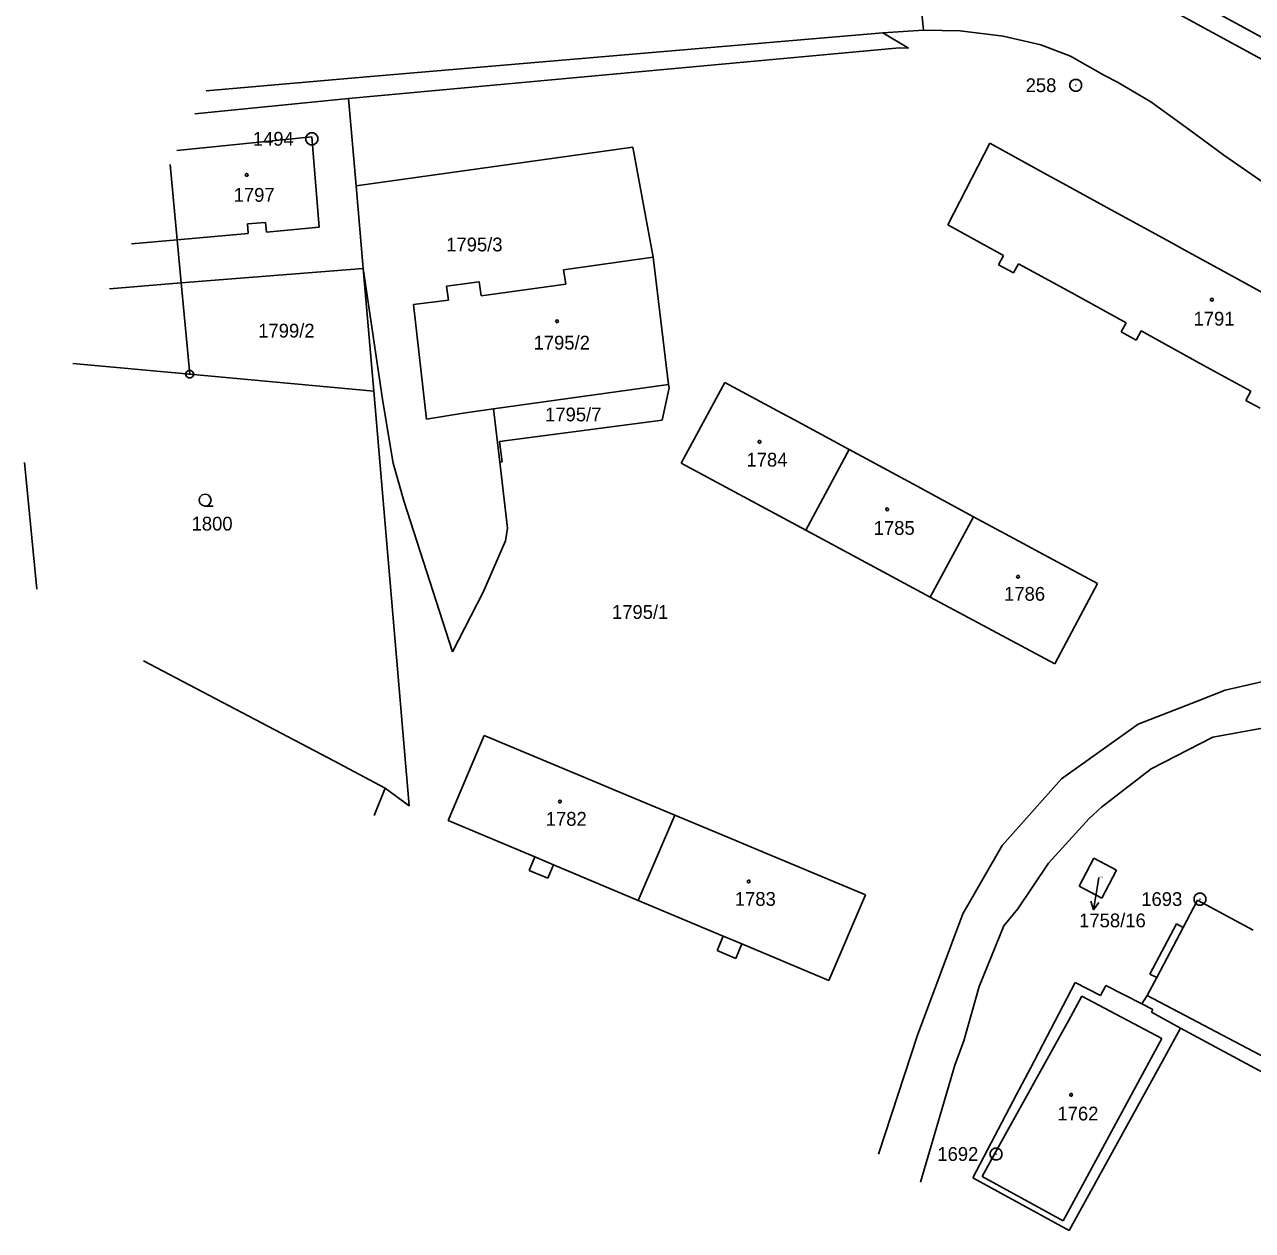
# Model space of a CAD drawing. Extents: x -528274 to -527531, y -1079304 to -1078580.
# Drawn here: x -528274.4 to -528123, y -1079056.9 to -1078908.2 of the extents above; entities that cross this region are included whole.
import ezdxf

# ---------------------------------------------------------------- set-up
doc = ezdxf.new("R2010")
doc.units = 0
doc.layers.add('katastrální mapa', color=7, linetype='Continuous')

msp = doc.modelspace()

# ---------------------------------------------------------------- linework, layer by layer
at = {"layer": 'katastrální mapa'}
for p, q in [((-528164.53, -1078898.32), (-528163.54, -1078908.83)), ((-528069.83, -1078938.11), (-528132.09, -1078904.11)), ((-528007.07, -1078975.18), (-528133.47, -1078906.09)), ((-528168.55, -1078909.17), (-528232.69, -1078914.64)), ((-528163.54, -1078908.83), (-528168.55, -1078909.17)), ((-528168.55, -1078909.17), (-528165.37, -1078911.05)), ((-528163.54, -1078908.83), (-528158.99, -1078908.92)), ((-528158.99, -1078908.92), (-528153.69, -1078909.6)), ((-528153.69, -1078909.6), (-528149.06, -1078910.66)), ((-528166.47, -1078911.04), (-528234.43, -1078917.27)), ((-528165.37, -1078911.05), (-528166.47, -1078911.04)), ((-528149.06, -1078910.66), (-528145.38, -1078912.05)), ((-528145.38, -1078912.05), (-528141.22, -1078914.44)), ((-528252, -1078916.32), (-528232.69, -1078914.64)), ((-528144.79, -1078915.64), (-528144.69, -1078915.64)), ((-528141.22, -1078914.44), (-528139.61, -1078915.25)), ((-528139.61, -1078915.25), (-528135.47, -1078917.68)), ((-528234.43, -1078917.27), (-528253.41, -1078919.19)), ((-528233.51, -1078928.06), (-528234.43, -1078917.27)), ((-528135.47, -1078917.68), (-528130.7, -1078921.13)), ((-528130.7, -1078921.13), (-528126.5, -1078924.27)), ((-528255.6, -1078923.69), (-528238.95, -1078922.01)), ((-528239.01, -1078922.25), (-528238.91, -1078922.25)), ((-528238.95, -1078922.01), (-528238.07, -1078933.14)), ((-528199.37, -1078923.27), (-528233.51, -1078928.06)), ((-528196.86, -1078936.86), (-528199.37, -1078923.27)), ((-528155.36, -1078922.8), (-528160.53, -1078932.88)), ((-528148.26, -1078926.69), (-528155.36, -1078922.8)), ((-528126.5, -1078924.27), (-528121.57, -1078927.7)), ((-528256.46, -1078925.44), (-528255.59, -1078934.71)), ((-528146.77, -1078927.51), (-528148.26, -1078926.69)), ((-528140.01, -1078931.21), (-528146.77, -1078927.51)), ((-528233.51, -1078928.06), (-528232.64, -1078938.27)), ((-528133.06, -1078935.02), (-528140.01, -1078931.21)), ((-528246.81, -1078933.95), (-528255.59, -1078934.71)), ((-528244.68, -1078932.57), (-528246.91, -1078932.76)), ((-528246.91, -1078932.76), (-528246.81, -1078933.95)), ((-528244.57, -1078933.76), (-528244.68, -1078932.57)), ((-528238.07, -1078933.14), (-528244.57, -1078933.76)), ((-528160.53, -1078932.88), (-528153.64, -1078936.66)), ((-528261.22, -1078935.19), (-528255.59, -1078934.71)), ((-528255.59, -1078934.71), (-528255.09, -1078940.04)), ((-528131.68, -1078935.77), (-528133.06, -1078935.02)), ((-528207.91, -1078938.4), (-528196.86, -1078936.86)), ((-528196.86, -1078936.86), (-528194.96, -1078952.55)), ((-528153.64, -1078936.66), (-528154.26, -1078937.8)), ((-528124.66, -1078939.62), (-528131.68, -1078935.77)), ((-528255.09, -1078940.04), (-528232.64, -1078938.27)), ((-528232.64, -1078938.27), (-528231.34, -1078953.37)), ((-528230.2, -1078954.68), (-528232.64, -1078938.27)), ((-528207.66, -1078940.2), (-528207.91, -1078938.4)), ((-528154.26, -1078937.8), (-528152.42, -1078938.8)), ((-528152.42, -1078938.8), (-528151.8, -1078937.67)), ((-528151.8, -1078937.67), (-528145.23, -1078941.27)), ((-528263.93, -1078940.74), (-528255.09, -1078940.04)), ((-528255.09, -1078940.04), (-528254.03, -1078951.3)), ((-528218.33, -1078939.9), (-528222.34, -1078940.43)), ((-528218.1, -1078941.61), (-528218.33, -1078939.9)), ((-528117.65, -1078943.46), (-528124.66, -1078939.62)), ((-528222.34, -1078940.43), (-528222.12, -1078942.14)), ((-528207.66, -1078940.2), (-528218.1, -1078941.61)), ((-528145.23, -1078941.27), (-528138.52, -1078944.95)), ((-528222.12, -1078942.14), (-528226.45, -1078942.71)), ((-528226.45, -1078942.71), (-528224.84, -1078956.83)), ((-528138.52, -1078944.95), (-528139.14, -1078946.07)), ((-528139.14, -1078946.07), (-528137.29, -1078947.08)), ((-528137.29, -1078947.08), (-528136.68, -1078945.96)), ((-528136.68, -1078945.96), (-528129.93, -1078949.67)), ((-528268.44, -1078949.98), (-528254.03, -1078951.3)), ((-528129.93, -1078949.67), (-528123.16, -1078953.38)), ((-528254.15, -1078951.3), (-528253.91, -1078951.3)), ((-528254.03, -1078951.3), (-528231.34, -1078953.37)), ((-528231.34, -1078953.37), (-528226.98, -1079004.55)), ((-528216.55, -1078955.58), (-528194.96, -1078952.55)), ((-528194.91, -1078952.97), (-528195.74, -1078956.97)), ((-528194.96, -1078952.55), (-528194.91, -1078952.97)), ((-528193.4, -1078962.25), (-528188.04, -1078952.31)), ((-528188.04, -1078952.31), (-528181, -1078956.11)), ((-528123.16, -1078953.38), (-528123.79, -1078954.52)), ((-528228.95, -1078962.25), (-528230.2, -1078954.68)), ((-528123.79, -1078954.52), (-528121.99, -1078955.5)), ((-528224.84, -1078956.83), (-528220.3, -1078956.11)), ((-528220.3, -1078956.11), (-528216.55, -1078955.58)), ((-528215.79, -1078962.13), (-528216.55, -1078955.58)), ((-528181, -1078956.11), (-528179.52, -1078956.9)), ((-528195.74, -1078956.97), (-528215.84, -1078959.61)), ((-528179.52, -1078956.9), (-528172.69, -1078960.59)), ((-528215.84, -1078959.61), (-528215.51, -1078962.09)), ((-528172.69, -1078960.59), (-528178.04, -1078970.52)), ((-528172.69, -1078960.59), (-528165.82, -1078964.29)), ((-528272.87, -1078977.83), (-528274.4, -1078962.2)), ((-528227.64, -1078966.91), (-528228.95, -1078962.25)), ((-528215.51, -1078962.09), (-528215.79, -1078962.13)), ((-528215.79, -1078962.13), (-528214.84, -1078970.28)), ((-528178.04, -1078970.52), (-528193.4, -1078962.25)), ((-528165.82, -1078964.29), (-528164.32, -1078965.1)), ((-528164.32, -1078965.1), (-528157.34, -1078968.87)), ((-528221.63, -1078985.54), (-528227.64, -1078966.91)), ((-528214.84, -1078970.28), (-528215.1, -1078971.85)), ((-528157.34, -1078968.87), (-528162.69, -1078978.78)), ((-528157.34, -1078968.87), (-528150.68, -1078972.46)), ((-528215.1, -1078971.85), (-528217.84, -1078978.19)), ((-528162.69, -1078978.78), (-528178.04, -1078970.52)), ((-528150.68, -1078972.46), (-528149.16, -1078973.28)), ((-528149.16, -1078973.28), (-528142.07, -1078977.1)), ((-528142.07, -1078977.1), (-528147.34, -1078987.04)), ((-528217.84, -1078978.19), (-528221.63, -1078985.54)), ((-528147.34, -1078987.04), (-528162.69, -1078978.78)), ((-528236.27, -1078999.01), (-528259.73, -1078986.65)), ((-528126.3, -1078990.26), (-528117, -1078988.13)), ((-528129.66, -1078991.6), (-528126.3, -1078990.26)), ((-528137.05, -1078994.47), (-528129.66, -1078991.6)), ((-528146.52, -1079001.22), (-528137.05, -1078994.47)), ((-528123.53, -1078995.3), (-528114.72, -1078993.64)), ((-528222.17, -1079006.35), (-528217.73, -1078995.86)), ((-528217.73, -1078995.86), (-528203.45, -1079001.82)), ((-528135.44, -1078999.98), (-528127.83, -1078996.06)), ((-528127.83, -1078996.06), (-528123.53, -1078995.3)), ((-528229.91, -1079002.36), (-528236.27, -1078999.01)), ((-528141.57, -1079004.7), (-528135.44, -1078999.98)), ((-528203.45, -1079001.82), (-528201.59, -1079002.6)), ((-528153.84, -1079009.45), (-528146.52, -1079001.22)), ((-528229.91, -1079002.36), (-528231.3, -1079005.74)), ((-528226.98, -1079004.55), (-528229.91, -1079002.36)), ((-528201.59, -1079002.6), (-528194.2, -1079005.69)), ((-528143.08, -1079006.1), (-528141.57, -1079004.7)), ((-528211.48, -1079010.84), (-528222.17, -1079006.35)), ((-528194.2, -1079005.69), (-528198.7, -1079016.21)), ((-528194.2, -1079005.69), (-528186.81, -1079008.77)), ((-528148.11, -1079011.63), (-528143.08, -1079006.1)), ((-528186.81, -1079008.77), (-528184.94, -1079009.55)), ((-528184.94, -1079009.55), (-528170.68, -1079015.51)), ((-528158.67, -1079017.88), (-528153.84, -1079009.45)), ((-528212.18, -1079012.51), (-528211.48, -1079010.84)), ((-528211.48, -1079010.84), (-528209.16, -1079011.82)), ((-528144.32, -1079014.46), (-528142.5, -1079011.01)), ((-528142.5, -1079011.01), (-528139.72, -1079012.48)), ((-528209.86, -1079013.48), (-528212.18, -1079012.51)), ((-528209.16, -1079011.82), (-528209.86, -1079013.48)), ((-528198.7, -1079016.21), (-528209.16, -1079011.82)), ((-528151.91, -1079017.26), (-528148.11, -1079011.63)), ((-528139.72, -1079012.48), (-528141.54, -1079015.92)), ((-528141.9, -1079013.4), (-528142.07, -1079014.4)), ((-528170.68, -1079015.51), (-528175.21, -1079026.08)), ((-528141.54, -1079015.92), (-528144.32, -1079014.46)), ((-528142.57, -1079017.36), (-528142.07, -1079014.4)), ((-528188.23, -1079020.61), (-528198.7, -1079016.21)), ((-528153.6, -1079019.34), (-528151.91, -1079017.26)), ((-528129.73, -1079016.2), (-528131.5, -1079019.55)), ((-528129.73, -1079016.2), (-528122.87, -1079019.88)), ((-528129.47, -1079016.05), (-528129.37, -1079016.05)), ((-528158.67, -1079017.88), (-528164.27, -1079032.84)), ((-528156.65, -1079026.82), (-528153.6, -1079019.34)), ((-528132.34, -1079019.1), (-528135.6, -1079025.3)), ((-528131.5, -1079019.55), (-528134.76, -1079025.74)), ((-528131.5, -1079019.55), (-528132.34, -1079019.1)), ((-528188.97, -1079022.39), (-528188.23, -1079020.61)), ((-528188.23, -1079020.61), (-528185.93, -1079021.58)), ((-528185.93, -1079021.58), (-528186.68, -1079023.36)), ((-528175.21, -1079026.08), (-528185.93, -1079021.58)), ((-528186.68, -1079023.36), (-528188.97, -1079022.39)), ((-528144.8, -1079026.32), (-528150.34, -1079036.89)), ((-528141.7, -1079027.95), (-528144.8, -1079026.32)), ((-528134.76, -1079025.74), (-528135.92, -1079027.95)), ((-528135.6, -1079025.3), (-528134.76, -1079025.74)), ((-528158.56, -1079033.55), (-528156.65, -1079026.82)), ((-528141.13, -1079026.86), (-528141.7, -1079027.95)), ((-528141.04, -1079026.72), (-528141.13, -1079026.86)), ((-528136.59, -1079028.99), (-528141.04, -1079026.72)), ((-528145.62, -1079030.98), (-528143.98, -1079028.03)), ((-528143.98, -1079028.03), (-528134.13, -1079033.24)), ((-528135.92, -1079027.95), (-528136.59, -1079028.99)), ((-528135.23, -1079029.68), (-528136.59, -1079028.99)), ((-528135.92, -1079027.95), (-528120.49, -1079036.1)), ((-528135.41, -1079030.01), (-528135.23, -1079029.68)), ((-528131.81, -1079031.96), (-528135.41, -1079030.01)), ((-528154.67, -1079047.35), (-528145.62, -1079030.98)), ((-528133.3, -1079034.67), (-528131.81, -1079031.96)), ((-528121.06, -1079037.78), (-528131.81, -1079031.96)), ((-528169.07, -1079047.5), (-528164.27, -1079032.84)), ((-528159.66, -1079036.53), (-528158.56, -1079033.55)), ((-528134.13, -1079033.24), (-528135.74, -1079036.23)), ((-528134.06, -1079036.05), (-528133.3, -1079034.67)), ((-528163.89, -1079050.98), (-528159.66, -1079036.53)), ((-528150.34, -1079036.89), (-528152.06, -1079040.16)), ((-528145.54, -1079056.93), (-528134.06, -1079036.05)), ((-528135.74, -1079036.23), (-528144.68, -1079052.79)), ((-528152.06, -1079040.16), (-528157.44, -1079050.43)), ((-528156.3, -1079050.29), (-528154.67, -1079047.35)), ((-528154.62, -1079047.5), (-528154.52, -1079047.5)), ((-528157.44, -1079050.43), (-528145.54, -1079056.93)), ((-528146.28, -1079055.76), (-528156.3, -1079050.29)), ((-528144.68, -1079052.79), (-528146.28, -1079055.76))]:
    msp.add_line(p, q, dxfattribs=at)
for points in [[(-528144.55, -1078914.92), (-528144.21, -1078915.11), (-528144.02, -1078915.45), (-528144.02, -1078915.84), (-528144.21, -1078916.18), (-528144.55, -1078916.37), (-528144.94, -1078916.37), (-528145.28, -1078916.18), (-528145.47, -1078915.84), (-528145.47, -1078915.45), (-528145.28, -1078915.11), (-528144.94, -1078914.92)], [(-528238.77, -1078921.53), (-528238.43, -1078921.72), (-528238.24, -1078922.06), (-528238.24, -1078922.45), (-528238.43, -1078922.79), (-528238.77, -1078922.98), (-528239.16, -1078922.98), (-528239.5, -1078922.79), (-528239.69, -1078922.45), (-528239.69, -1078922.06), (-528239.5, -1078921.72), (-528239.16, -1078921.53)], [(-528247.01, -1078926.54), (-528246.91, -1078926.56), (-528246.86, -1078926.65), (-528246.84, -1078926.71), (-528246.86, -1078926.8), (-528246.94, -1078926.87), (-528247.01, -1078926.88), (-528247.1, -1078926.85), (-528247.16, -1078926.79), (-528247.18, -1078926.71), (-528247.16, -1078926.62), (-528247.08, -1078926.55)], [(-528127.96, -1078941.93), (-528127.86, -1078941.95), (-528127.81, -1078942.04), (-528127.79, -1078942.1), (-528127.81, -1078942.19), (-528127.89, -1078942.26), (-528127.96, -1078942.27), (-528128.05, -1078942.24), (-528128.11, -1078942.18), (-528128.13, -1078942.1), (-528128.11, -1078942.01), (-528128.03, -1078941.94)], [(-528208.72, -1078944.6), (-528208.62, -1078944.62), (-528208.57, -1078944.71), (-528208.55, -1078944.77), (-528208.57, -1078944.86), (-528208.65, -1078944.93), (-528208.72, -1078944.94), (-528208.81, -1078944.91), (-528208.87, -1078944.85), (-528208.89, -1078944.77), (-528208.87, -1078944.68), (-528208.79, -1078944.61)], [(-528253.88, -1078950.82), (-528253.63, -1078951), (-528253.53, -1078951.29), (-528253.63, -1078951.58), (-528253.88, -1078951.76), (-528254.19, -1078951.76), (-528254.44, -1078951.58), (-528254.54, -1078951.29), (-528254.44, -1078951), (-528254.19, -1078950.82)], [(-528183.76, -1078959.46), (-528183.66, -1078959.48), (-528183.61, -1078959.57), (-528183.59, -1078959.63), (-528183.61, -1078959.72), (-528183.69, -1078959.79), (-528183.76, -1078959.8), (-528183.85, -1078959.77), (-528183.91, -1078959.71), (-528183.93, -1078959.63), (-528183.91, -1078959.54), (-528183.83, -1078959.47)], [(-528168.01, -1078967.79), (-528167.91, -1078967.81), (-528167.86, -1078967.9), (-528167.84, -1078967.96), (-528167.86, -1078968.05), (-528167.94, -1078968.12), (-528168.01, -1078968.13), (-528168.1, -1078968.1), (-528168.16, -1078968.04), (-528168.18, -1078967.96), (-528168.16, -1078967.87), (-528168.08, -1078967.8)], [(-528151.87, -1078976.11), (-528151.77, -1078976.13), (-528151.72, -1078976.22), (-528151.7, -1078976.28), (-528151.72, -1078976.37), (-528151.8, -1078976.44), (-528151.87, -1078976.45), (-528151.96, -1078976.42), (-528152.02, -1078976.36), (-528152.04, -1078976.28), (-528152.02, -1078976.19), (-528151.94, -1078976.12)], [(-528208.37, -1079003.85), (-528208.27, -1079003.87), (-528208.22, -1079003.96), (-528208.2, -1079004.02), (-528208.22, -1079004.11), (-528208.3, -1079004.18), (-528208.37, -1079004.19), (-528208.46, -1079004.16), (-528208.52, -1079004.1), (-528208.54, -1079004.02), (-528208.52, -1079003.93), (-528208.44, -1079003.86)], [(-528185.1, -1079013.71), (-528185, -1079013.73), (-528184.95, -1079013.82), (-528184.93, -1079013.88), (-528184.95, -1079013.97), (-528185.03, -1079014.04), (-528185.1, -1079014.05), (-528185.19, -1079014.02), (-528185.25, -1079013.96), (-528185.27, -1079013.88), (-528185.25, -1079013.79), (-528185.17, -1079013.72)], [(-528129.23, -1079015.33), (-528128.89, -1079015.52), (-528128.7, -1079015.86), (-528128.7, -1079016.25), (-528128.89, -1079016.59), (-528129.23, -1079016.78), (-528129.62, -1079016.78), (-528129.96, -1079016.59), (-528130.15, -1079016.25), (-528130.15, -1079015.86), (-528129.96, -1079015.52), (-528129.62, -1079015.33)], [(-528145.32, -1079040.03), (-528145.22, -1079040.05), (-528145.17, -1079040.14), (-528145.15, -1079040.2), (-528145.17, -1079040.29), (-528145.25, -1079040.36), (-528145.32, -1079040.37), (-528145.41, -1079040.34), (-528145.47, -1079040.28), (-528145.49, -1079040.2), (-528145.47, -1079040.11), (-528145.39, -1079040.04)], [(-528154.38, -1079046.78), (-528154.04, -1079046.97), (-528153.85, -1079047.31), (-528153.85, -1079047.7), (-528154.04, -1079048.04), (-528154.38, -1079048.23), (-528154.77, -1079048.23), (-528155.11, -1079048.04), (-528155.3, -1079047.7), (-528155.3, -1079047.31), (-528155.11, -1079046.97), (-528154.77, -1079046.78)]]:
    msp.add_lwpolyline(points, close=True, dxfattribs=at)
for points in [[(-528252.13, -1078967.57), (-528252.51, -1078967.47), (-528252.78, -1078967.2), (-528252.88, -1078966.83), (-528252.78, -1078966.46), (-528252.51, -1078966.19), (-528252.14, -1078966.09), (-528251.77, -1078966.19), (-528251.5, -1078966.46), (-528251.4, -1078966.84), (-528251.5, -1078967.22), (-528251.77, -1078967.49), (-528252.15, -1078967.59), (-528251.15, -1078967.59)], [(-528141.91, -1079016.46), (-528142.57, -1079017.36), (-528142.89, -1079016.29)]]:
    msp.add_lwpolyline(points, dxfattribs=at)

# ---------------------------------------------------------------- texts
for s, height, p in [('258', 1.7, (-528150.93, -1078916.49)), ('1494', 1.7, (-528246.25, -1078923.1)), ('1797', 1.7, (-528248.61, -1078930.02)), ('1795/3', 1.7, (-528222.4, -1078936.14)), ('1791', 1.7, (-528130.22, -1078945.29)), ('1799/2', 1.7, (-528245.58, -1078946.77)), ('1795/2', 1.7, (-528211.62, -1078948.25)), ('1795/7', 1.7, (-528210.2, -1078957.11)), ('1784', 1.7, (-528185.36, -1078962.69)), ('1800', 1.7, (-528253.8, -1078970.58)), ('1785', 1.7, (-528169.67, -1078971.11)), ('1786', 1.7, (-528153.59, -1078979.24)), ('1795/1', 1.7, (-528201.95, -1078981.48)), ('1782', 1.7, (-528210.12, -1079007)), ('1758/16', 0.1, (-528141.88, -1079013.4)), ('1783', 1.7, (-528186.8, -1079016.88)), ('1693', 1.7, (-528136.67, -1079016.9)), ('1758/16', 1.7, (-528144.33, -1079019.53)), ('1762', 1.7, (-528147.01, -1079043.36)), ('1692', 1.7, (-528161.82, -1079048.35))]:
    msp.add_text(s, height=height, dxfattribs=at).set_placement(p)

doc.saveas('drawing.dxf')
